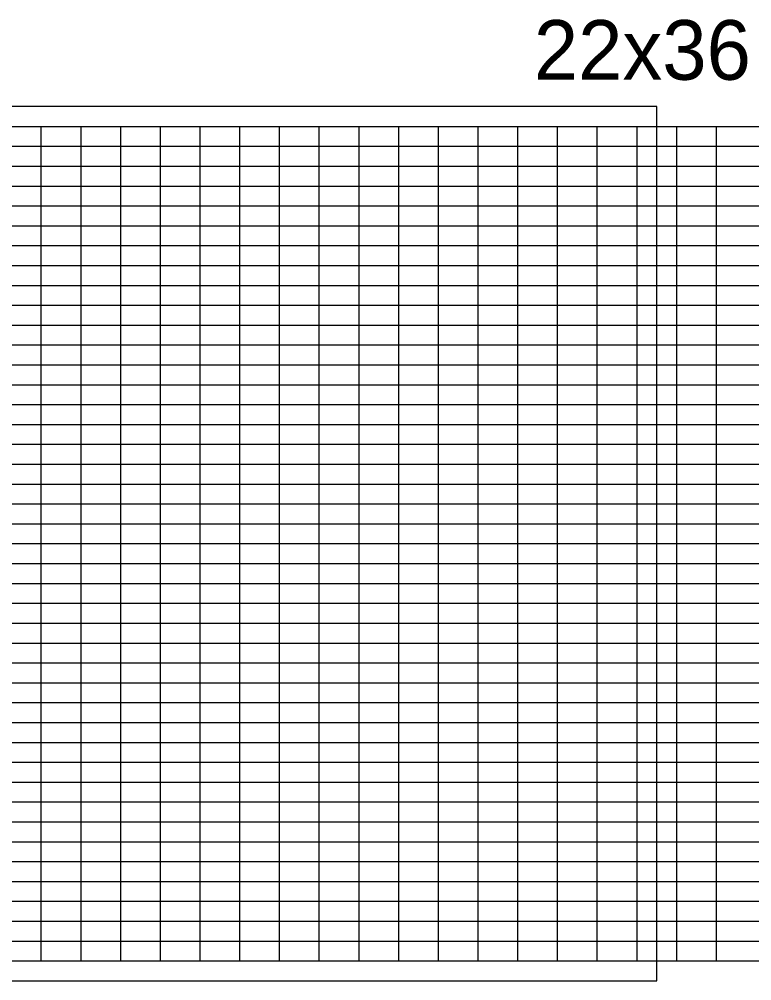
# Model space of a CAD drawing. Extents: x 1873632 to 1926512, y 813126 to 836257.
# Drawn here: x 1884585 to 1885508, y 820500 to 821710 of the extents above; entities that cross this region are included whole.
import ezdxf

# ---------------------------------------------------------------- set-up
doc = ezdxf.new("R2010")
doc.units = 0
doc.layers.add('RD_PD_WallFill', color=7, linetype='Continuous')
doc.layers.add('RD_SHT_IplotShp', color=7, linetype='Continuous')

msp = doc.modelspace()

# ---------------------------------------------------------------- linework, layer by layer
at = {"layer": 'RD_PD_WallFill'}
for p, q in [((1883663.1, 821575.1), (1889013.1, 821575.1)), ((1883663.1, 821575.1), (1885413.1, 821575.1)), ((1884613.1, 820525.1), (1884613.1, 821575.1)), ((1884613.1, 820525.1), (1884613.1, 821575.1)), ((1884663.1, 820525.1), (1884663.1, 821575.1)), ((1884663.1, 820525.1), (1884663.1, 821575.1)), ((1884713.1, 820525.1), (1884713.1, 821575.1)), ((1884713.1, 820525.1), (1884713.1, 821575.1)), ((1884763.1, 820525.1), (1884763.1, 821575.1)), ((1884763.1, 820525.1), (1884763.1, 821575.1)), ((1884813.1, 820525.1), (1884813.1, 821575.1)), ((1884813.1, 820525.1), (1884813.1, 821575.1)), ((1884863.1, 820525.1), (1884863.1, 821575.1)), ((1884863.1, 820525.1), (1884863.1, 821575.1)), ((1884913.1, 820525.1), (1884913.1, 821575.1)), ((1884913.1, 820525.1), (1884913.1, 821575.1)), ((1884963.1, 820525.1), (1884963.1, 821575.1)), ((1884963.1, 820525.1), (1884963.1, 821575.1)), ((1885013.1, 820525.1), (1885013.1, 821575.1)), ((1885013.1, 820525.1), (1885013.1, 821575.1)), ((1885063.1, 820525.1), (1885063.1, 821575.1)), ((1885063.1, 820525.1), (1885063.1, 821575.1)), ((1885113.1, 820525.1), (1885113.1, 821575.1)), ((1885113.1, 820525.1), (1885113.1, 821575.1)), ((1885163.1, 820525.1), (1885163.1, 821575.1)), ((1885163.1, 820525.1), (1885163.1, 821575.1)), ((1885213.1, 820525.1), (1885213.1, 821575.1)), ((1885213.1, 820525.1), (1885213.1, 821575.1)), ((1885263.1, 820525.1), (1885263.1, 821575.1)), ((1885263.1, 820525.1), (1885263.1, 821575.1)), ((1885313.1, 820525.1), (1885313.1, 821575.1)), ((1885313.1, 820525.1), (1885313.1, 821575.1)), ((1885363.1, 820525.1), (1885363.1, 821575.1)), ((1885363.1, 820525.1), (1885363.1, 821575.1)), ((1885413.1, 820525.1), (1885413.1, 821575.1)), ((1885413.1, 820525.1), (1885413.1, 821575.1)), ((1885463.1, 820525.1), (1885463.1, 821575.1)), ((1885463.1, 820525.1), (1885463.1, 821575.1)), ((1884113.1, 821550.1), (1889013.1, 821550.1)), ((1884113.1, 821550.1), (1889013.1, 821550.1)), ((1884113.1, 821525.1), (1889013.1, 821525.1)), ((1884113.1, 821500.1), (1889013.1, 821500.1)), ((1884113.1, 821475.1), (1889013.1, 821475.1)), ((1884113.1, 821450.1), (1889013.1, 821450.1)), ((1883663.1, 821425.1), (1889013.1, 821425.1)), ((1883663.1, 821400.1), (1889013.1, 821400.1)), ((1883663.1, 821375.1), (1889013.1, 821375.1)), ((1883663.1, 821350.1), (1889013.1, 821350.1)), ((1883663.1, 821325.1), (1889013.1, 821325.1)), ((1883663.1, 821300.1), (1889013.1, 821300.1)), ((1883663.1, 821275.1), (1889013.1, 821275.1)), ((1883663.1, 821250.1), (1889013.1, 821250.1)), ((1883663.1, 821225.1), (1889013.1, 821225.1)), ((1883663.1, 821200.1), (1889013.1, 821200.1)), ((1883663.1, 821175.1), (1889013.1, 821175.1)), ((1883663.1, 821150.1), (1889013.1, 821150.1)), ((1883663.1, 821125.1), (1889013.1, 821125.1)), ((1883663.1, 821100.1), (1889013.1, 821100.1)), ((1883663.1, 821075.1), (1889013.1, 821075.1)), ((1883663.1, 821050.1), (1889013.1, 821050.1)), ((1883663.1, 821025.1), (1889013.1, 821025.1)), ((1883663.1, 821000.1), (1889013.1, 821000.1)), ((1883663.1, 820975.1), (1889013.1, 820975.1)), ((1883663.1, 820950.1), (1889013.1, 820950.1)), ((1883663.1, 820925.1), (1889013.1, 820925.1)), ((1883663.1, 820900.1), (1889013.1, 820900.1)), ((1883663.1, 820875.1), (1889013.1, 820875.1)), ((1883663.1, 820850.1), (1889013.1, 820850.1)), ((1883663.1, 820825.1), (1889013.1, 820825.1)), ((1883663.1, 820800.1), (1889013.1, 820800.1)), ((1883663.1, 820775.1), (1889013.1, 820775.1)), ((1883663.1, 820750.1), (1889013.1, 820750.1)), ((1883663.1, 820725.1), (1889013.1, 820725.1)), ((1883663.1, 820700.1), (1889013.1, 820700.1)), ((1883663.1, 820675.1), (1889013.1, 820675.1)), ((1883663.1, 820650.1), (1889013.1, 820650.1)), ((1883663.1, 820625.1), (1889013.1, 820625.1)), ((1883663.1, 820600.1), (1889013.1, 820600.1)), ((1883663.1, 820575.1), (1889013.1, 820575.1)), ((1883663.1, 820550.1), (1889013.1, 820550.1)), ((1883663.1, 820525.1), (1889013.1, 820525.1)), ((1883663.1, 820525.1), (1889013.1, 820525.1))]:
    msp.add_line(p, q, dxfattribs=at)
at = {"layer": 'RD_SHT_IplotShp'}
msp.add_lwpolyline([(1883638.1, 820500.1), (1885388.1, 820500.1), (1885388.1, 821600.1), (1883638.1, 821600.1)], close=True, dxfattribs=at)

# ---------------------------------------------------------------- texts
at = {"layer": 'RD_PD_WallFill'}
msp.add_text('22x36', height=75, dxfattribs=at).set_placement((1885233.2, 821633.8))
msp.add_text('22x36', height=75, dxfattribs=at).set_placement((1885233.2, 821633.8))

doc.saveas('drawing.dxf')
